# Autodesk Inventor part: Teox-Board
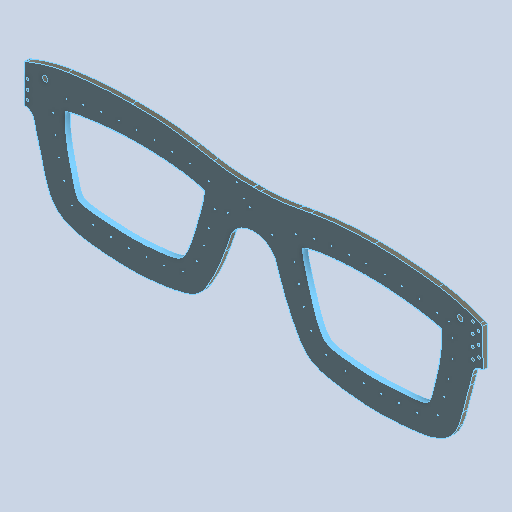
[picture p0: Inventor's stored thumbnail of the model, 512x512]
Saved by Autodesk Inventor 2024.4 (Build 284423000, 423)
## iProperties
Created: 2025-05
Part Number: Teox-Board
Material: Generic
Document SubType Name: Modeling
Designer: AdminForWorker
Density: 1 g/cm^3
Appearance: Default
Title: Teox-Board
Author: AdminForWorker
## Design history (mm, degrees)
feature "Body1"
body "Solid1"
